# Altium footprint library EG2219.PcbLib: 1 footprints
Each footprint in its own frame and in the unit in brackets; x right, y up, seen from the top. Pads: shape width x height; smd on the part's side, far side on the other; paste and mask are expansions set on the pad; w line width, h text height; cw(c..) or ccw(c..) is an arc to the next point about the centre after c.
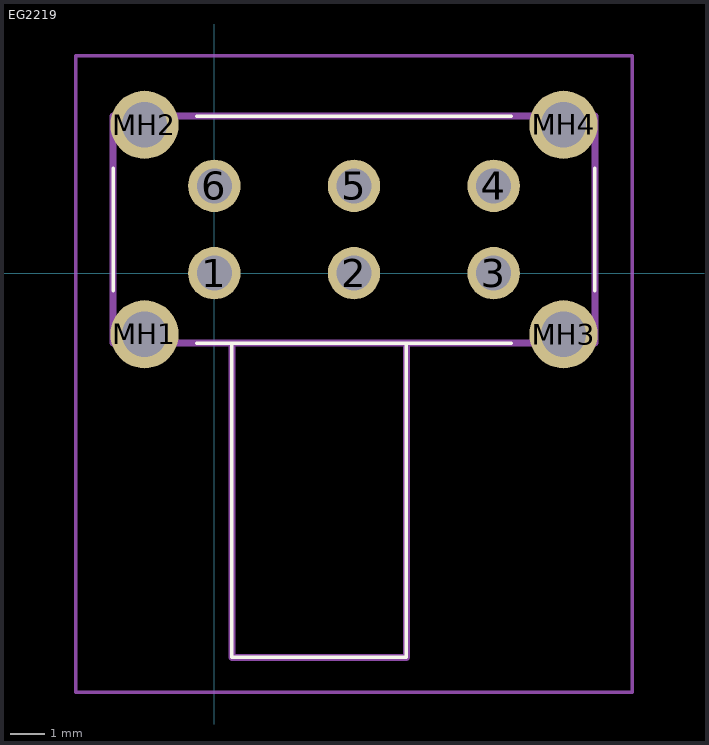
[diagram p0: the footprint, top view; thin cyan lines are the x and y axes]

## EG2219 [mm]
pads (10):
  round 1.5 hole 1: 1(0,0) 2(4,0) 3(8,0) 4(8,2.5) 5(4,2.5) 6(0,2.5)
  round 1.95 hole 1.3: MH1(-2,-1.75) MH2(-2,4.25) MH3(10,-1.75) MH4(10,4.25)
Top Overlay:
  lines w0.1: -2.9,-0.5 -2.9,3 ; -0.5,-2 8.5,-2 ; -0.5,4.5 8.5,4.5 ; 0.5,-2 0.5,-11 5.5,-11 5.5,-2 ; 10.9,-0.5 10.9,3
Mechanical 15:
  lines w0.2: 0.5,-2 0.5,-11 5.5,-11 5.5,-2 ; -2.9,-2 10.9,-2 10.9,4.5 -2.9,4.5 -2.9,-2
Mechanical 20:
  lines w0.1: -3.975,-12 11.975,-12 11.975,6.225 -3.975,6.225 -3.975,-12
